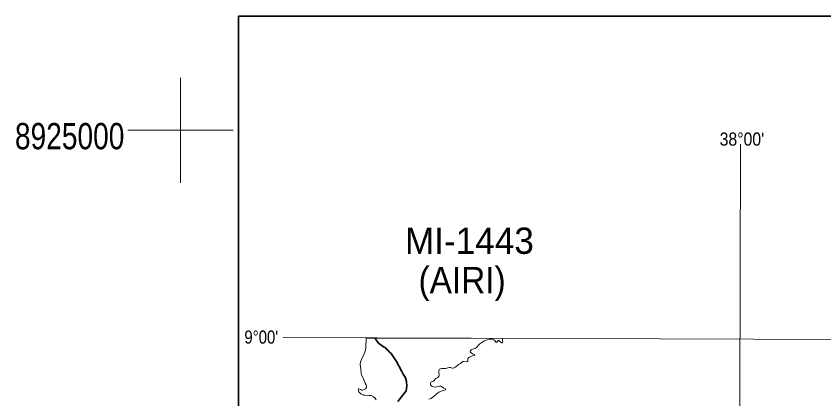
# Model space of a CAD drawing. Extents: x 553962 to 842807, y 8883888 to 9032388.
# Drawn here: x 571872 to 587242, y 8919892 to 8927171 of the extents above; entities that cross this region are included whole.
import ezdxf
from ezdxf.enums import TextEntityAlignment as Align

# ---------------------------------------------------------------- set-up
doc = ezdxf.new("R2010")
doc.units = 0
doc.header["$LTSCALE"] = 160
doc.linetypes.add('LONG_DASH_SHORT_DASH', pattern=[9.9, 6, -1.2, 1.5, -1.2])
doc.layers.add('1', color=7, linetype='Continuous', lineweight=13)
doc.layers.add('6', color=7, linetype='Continuous', lineweight=13)

msp = doc.modelspace()

# ---------------------------------------------------------------- linework, layer by layer
at = {"layer": '1'}
for p, q in [((575000, 8924000), (575000, 8926000)), ((574000, 8925000), (576000, 8925000))]:
    msp.add_line(p, q, dxfattribs=at)
at = {"layer": '6'}
msp.add_line((581121.2, 8921038.8), (578531.5, 8921044.3), dxfattribs=at)
at = {"layer": '6', "lineweight": 35}
msp.add_lwpolyline([(576104.8, 8927170.9), (624533.7, 8927170.9), (624533.7, 8897728.1), (576104.8, 8897728.1)], close=True, dxfattribs=at)
at = {"layer": '6'}
for points in [[(585656.3, 8924738.8), (585614.8, 8909969.8), (585579.9, 8898162.7)], [(576954.6, 8921057), (596639.8, 8920989.8), (607636.3, 8920937.2), (623613.9, 8920839.1)], [(578531.5, 8921044.3), (578525.4, 8920861.1), (578521, 8920819.7), (578490.8, 8920729.8), (578464.8, 8920681.3), (578427.7, 8920597.6), (578420.3, 8920542.1), (578424.2, 8920499.8), (578432.8, 8920469.4), (578439.3, 8920370.1), (578446.7, 8920342.4), (578476.9, 8920285.4), (578512.4, 8920187.2), (578534, 8920155.6), (578541.8, 8920127.9), (578541.8, 8920108.5), (578520.6, 8920080.8), (578496, 8920066.1), (578459.8, 8920053.6), (578441.4, 8920053.6), (578423.4, 8920067.4), (578392.2, 8920079.5), (578384, 8920077.7), (578378.4, 8920063.1), (578394.4, 8920026.8), (578431.9, 8919986.2), (578483, 8919962.8), (578507.1, 8919958.9), (578585.1, 8919958), (578628.8, 8919952.9), (578664.6, 8919935.5), (578704.8, 8919902.2), (578724.3, 8919870.2)], [(579725.6, 8919882.8), (579767.1, 8919897.1), (579839.7, 8919952.8), (579883, 8919994.7), (579914.9, 8920018.5), (579956.5, 8920036.3), (580025.6, 8920054.4), (580039.4, 8920065.7), (580043.3, 8920072.7), (580039.4, 8920083), (580010, 8920094.7), (579966.9, 8920124.4), (579951.3, 8920131.8), (579930.5, 8920133.6), (579875.2, 8920117.1), (579840.6, 8920115.8), (579783.6, 8920134.8), (579758.8, 8920158.4), (579754.6, 8920184.2), (579761.9, 8920206.2), (579774.5, 8920217), (579813.8, 8920225.3), (579860.1, 8920275.4), (579895.5, 8920300.4), (579913.9, 8920318.8), (579921.6, 8920350.7), (579915.8, 8920390.8), (579915.4, 8920422), (579918, 8920433.2), (579931, 8920453.1), (579965, 8920468.6), (580042.9, 8920468.2), (580110.4, 8920489.4), (580135, 8920486.7), (580169.2, 8920474.7), (580182.1, 8920474.7), (580209.9, 8920482.9), (580232.8, 8920495.5), (580286.8, 8920543.9), (580330.1, 8920563.4), (580370.3, 8920600.1), (580392.2, 8920604), (580447.8, 8920597.7), (580462.7, 8920600.1), (580468.1, 8920609.3), (580465.4, 8920649.4), (580481.8, 8920671.8), (580500.4, 8920686.3), (580558.2, 8920706.8), (580587.8, 8920713.2), (580598.4, 8920722.8), (580593.6, 8920732.5), (580556.5, 8920749.3), (580522.5, 8920773), (580513.8, 8920785.1), (580515.5, 8920802.9), (580532.8, 8920821), (580553.6, 8920834), (580604.1, 8920848.2), (580639.6, 8920872.9), (580666.9, 8920910.2), (580696.6, 8920937.3), (580749.4, 8920976.7), (580780.5, 8920993.1), (580834, 8921014.6), (580880.7, 8921023.8), (580934, 8921026.4), (580962.9, 8921016.4), (580979.4, 8921004.4), (581002.3, 8920972.3), (581011.8, 8920966.3), (581020.4, 8920969.7), (581025.8, 8920985.4), (581044.8, 8921001.3), (581055.1, 8920999.5), (581110, 8920959.3), (581125.1, 8920955.5), (581132, 8920968.4), (581121.2, 8921038.8)]]:
    msp.add_lwpolyline(points, dxfattribs=at)
at = {"layer": '6', "linetype": 'LONG_DASH_SHORT_DASH', "lineweight": 35}
msp.add_lwpolyline([(578702.1, 8921041.7), (578732.5, 8920996.5), (578770, 8920953.4), (578860.1, 8920883.7), (578900.2, 8920859.1), (578930.9, 8920824.9), (578945.6, 8920814.5), (578976.3, 8920780.8), (579009.1, 8920751.4), (579036, 8920715.1), (579057.2, 8920678.8), (579111.6, 8920601.8), (579159.6, 8920505), (579214.2, 8920410.6), (579239.6, 8920358), (579263.4, 8920321.7), (579278.1, 8920289.2), (579298, 8920220.5), (579306.6, 8920132.3), (579291, 8920043.1), (579137.8, 8919842.8)], dxfattribs=at)

# ---------------------------------------------------------------- texts
at = {"layer": '1', "width": 0.8}
msp.add_text('8925000', height=500, dxfattribs=at).set_placement((572890.2, 8924638.8), align=Align.CENTER)
at = {"layer": '6'}
for s, width, p in [("38°00'", 0.9, (585681.9, 8924707.6)), ("9°00'", 0.85, (576536.1, 8920941.3))]:
    msp.add_text(s, height=250, dxfattribs=dict(at, width=width)).set_placement(p, align=Align.CENTER)
msp.add_text('MI-1443', height=500, dxfattribs=at).set_placement((579270.9, 8922649.4))
at = {"layer": '6', "width": 0.95}
msp.add_text('(AIRI)', height=500, dxfattribs=at).set_placement((579529, 8921901.6))

doc.saveas('drawing.dxf')
